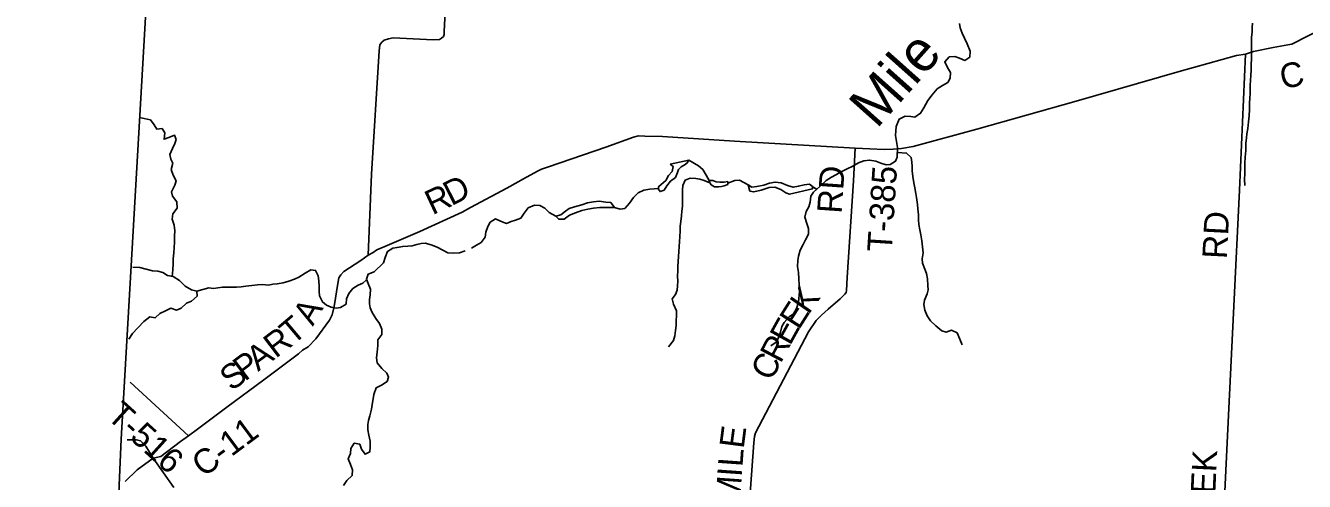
# Model space of a CAD drawing. Extents: x 1759416 to 2214760, y 252598 to 1116833.
# Drawn here: x 1928341 to 1943940, y 885193 to 890747 of the extents above; entities that cross this region are included whole.
import ezdxf

# ---------------------------------------------------------------- set-up
doc = ezdxf.new("R2010")
doc.units = 0
for name, color, linetype in [('GM_X_Adjacent_County', 7, 'Continuous'), ('GM_X_County', 7, 'Continuous'), ('GM_X_County_Road', 7, 'Continuous'), ('GM_X_County_Road_Text', 7, 'Continuous'), ('GM_X_Minor_Lake', 7, 'Continuous'), ('GM_X_Minor_River', 7, 'Continuous'), ('GM_X_Minor_River_Text', 7, 'Continuous'), ('GM_X_Township', 7, 'Continuous'), ('GM_X_Township_Road', 7, 'Continuous'), ('GM_X_Township_Road_Text', 7, 'Continuous')]:
    doc.layers.add(name, color=color, linetype=linetype)

msp = doc.modelspace()

# ---------------------------------------------------------------- linework, layer by layer
at = {"layer": 'GM_X_Adjacent_County'}
msp.add_lwpolyline([(1929994, 894165), (1929509, 885709), (1929483, 885147), (1929313, 880637), (1929312, 880613), (1928987, 876105), (1928954, 875572), (1928932, 875213), (1928849, 873883), (1928341, 865325)], dxfattribs=at)
at = {"layer": 'GM_X_County'}
msp.add_lwpolyline([(1928341, 865325), (1928849, 873883), (1928932, 875213), (1928954, 875572), (1928987, 876105), (1929312, 880613), (1929313, 880637), (1929483, 885147), (1929509, 885709), (1929994, 894165)], dxfattribs=at)
at = {"layer": 'GM_X_County_Road'}
for points in [[(1943220, 890401), (1943220, 890401), (1943318, 890430), (1943557, 890479), (1943736, 890512), (1943786, 890522), (1943987, 890621), (1944395, 890822)], [(1929555, 885194), (1929704, 885336), (1929899, 885475), (1929991, 885498), (1930230, 885678), (1930327, 885749), (1930438, 885830), (1930794, 886098), (1931246, 886433), (1931669, 886746), (1931717, 886793), (1931790, 886835), (1931880, 886932), (1932050, 887157), (1932081, 887223), (1932105, 887325), (1932148, 887605), (1932162, 887675), (1932185, 887709), (1932221, 887751), (1932432, 887885), (1932520, 887949), (1932579, 887984), (1932625, 888014), (1932725, 888057), (1933149, 888238), (1933665, 888474), (1933767, 888530), (1934213, 888768), (1934450, 888899), (1934595, 888979), (1934635, 888999), (1934718, 889028), (1935419, 889267), (1935756, 889386), (1935818, 889403), (1935896, 889401), (1936111, 889396), (1936988, 889341), (1938460, 889252), (1938638, 889245), (1938812, 889238), (1938925, 889243), (1939027, 889251), (1939169, 889272), (1939944, 889486), (1941157, 889825), (1942411, 890187), (1943112, 890383), (1943220, 890401)], [(1941368, 880620), (1941940, 881566), (1942051, 881746), (1942090, 881824), (1942112, 881902), (1942129, 882056), (1942148, 882437), (1942167, 882546), (1942181, 882630), (1942214, 882720), (1942261, 882832), (1942334, 882952), (1942494, 882949), (1942752, 882944), (1942810, 882939), (1942863, 882935), (1942887, 883358), (1942937, 884398), (1943014, 886001), (1943079, 887327), (1943149, 888741), (1943220, 890401)], [(1929581, 885699), (1929695, 885698), (1929744, 885687), (1929774, 885657), (1929808, 885621), (1929899, 885475)], [(1929899, 885475), (1930151, 885119)]]:
    msp.add_lwpolyline(points, dxfattribs=at)
at = {"layer": 'GM_X_Minor_Lake'}
for points in [[(1936203, 889059), (1936221, 889045), (1936239, 889031), (1936226, 888971), (1936182, 888920), (1936149, 888858), (1936095, 888811), (1936065, 888787), (1936059, 888757), (1936080, 888725), (1936130, 888741), (1936163, 888794), (1936209, 888852), (1936268, 888895), (1936294, 888956), (1936303, 888994), (1936339, 889026), (1936385, 889055), (1936411, 889073), (1936431, 889106)], [(1936431, 889106), (1936203, 889059)], [(1936908, 888848), (1936860, 888840), (1936810, 888839), (1936764, 888845), (1936724, 888858), (1936710, 888860), (1936684, 888858), (1936684, 888840), (1936704, 888808), (1936744, 888782), (1936791, 888783), (1936829, 888787), (1936861, 888796), (1936905, 888810)], [(1936905, 888810), (1936908, 888848)], [(1937174, 888729), (1937222, 888721), (1937312, 888740), (1937412, 888776), (1937482, 888780), (1937554, 888751), (1937613, 888708), (1937657, 888694), (1937939, 888757), (1937941, 888788), (1937904, 888815), (1937838, 888808), (1937768, 888792), (1937704, 888777), (1937634, 888798), (1937556, 888833), (1937483, 888841), (1937413, 888826), (1937347, 888803), (1937259, 888786), (1937199, 888779), (1937153, 888805)], [(1937153, 888805), (1937174, 888729)], [(1935526, 888532), (1935478, 888590), (1935418, 888595), (1935339, 888608), (1935269, 888599), (1935195, 888586), (1935125, 888564), (1935035, 888539), (1934973, 888520), (1934928, 888487), (1934870, 888442), (1934810, 888426)], [(1934810, 888426), (1934845, 888388), (1934909, 888387), (1934974, 888438), (1935050, 888467), (1935124, 888493), (1935198, 888510), (1935268, 888521), (1935346, 888530), (1935422, 888529), (1935464, 888531), (1935526, 888532)]]:
    msp.add_lwpolyline(points, dxfattribs=at)
at = {"layer": 'GM_X_Minor_River'}
for points in [[(1939733, 890771), (1939739, 890721), (1939766, 890653), (1939793, 890595), (1939827, 890525), (1939862, 890435), (1939859, 890363), (1939797, 890322), (1939731, 890352), (1939675, 890369), (1939607, 890366), (1939553, 890304), (1939588, 890236), (1939624, 890174), (1939617, 890106), (1939590, 890055), (1939526, 890019), (1939460, 889976), (1939401, 889905), (1939345, 889834), (1939296, 889747), (1939257, 889679), (1939187, 889632), (1939137, 889639), (1939069, 889644), (1938995, 889608), (1938960, 889517), (1938954, 889463), (1938951, 889410), (1938963, 889334), (1938976, 889260), (1938973, 889144), (1938952, 889094), (1938888, 889055), (1938838, 889050), (1938774, 889072), (1938713, 889095), (1938635, 889108), (1938565, 889099), (1938501, 889075), (1938425, 889032), (1938370, 889007), (1938296, 888968), (1938224, 888929), (1938172, 888900), (1938108, 888860), (1938033, 888789)], [(1943306, 890777), (1943304, 890724), (1943301, 890670), (1943294, 890602), (1943292, 890528), (1943294, 890409), (1943292, 890347), (1943291, 890269), (1943290, 890203), (1943286, 890145), (1943283, 890080), (1943279, 890022), (1943278, 889972), (1943276, 889920), (1943275, 889864), (1943269, 889801), (1943270, 889723), (1943265, 889647), (1943256, 889575), (1943248, 889494), (1943239, 889430), (1943232, 889378), (1943224, 889312), (1943223, 889227), (1943216, 889145), (1943211, 889071), (1943212, 888942), (1943207, 888876), (1943213, 888800)], [(1930129, 887691), (1930138, 887771), (1930141, 887847), (1930143, 887907), (1930150, 887979), (1930154, 888045), (1930157, 888109), (1930159, 888185), (1930160, 888245), (1930154, 888315), (1930131, 888390), (1930137, 888454), (1930192, 888522), (1930186, 888598), (1930135, 888670), (1930123, 888720), (1930160, 888802), (1930176, 888856), (1930143, 888924), (1930117, 888993), (1930136, 889071), (1930112, 889121), (1930099, 889177), (1930135, 889249), (1930162, 889309), (1930176, 889361), (1930159, 889411), (1930088, 889384), (1930030, 889362), (1930041, 889440), (1930007, 889494), (1929941, 889487), (1929911, 889537), (1929864, 889598), (1929748, 889624)], [(1938975, 889202), (1939087, 889193), (1939142, 889138), (1939152, 889084), (1939155, 889032), (1939155, 888976), (1939164, 888907), (1939177, 888833), (1939188, 888769), (1939198, 888703), (1939207, 888651), (1939220, 888567), (1939226, 888515), (1939231, 888441), (1939231, 888379), (1939236, 888325), (1939247, 888259), (1939259, 888199), (1939272, 888124), (1939281, 888052), (1939290, 887978), (1939278, 887904), (1939283, 887852), (1939310, 887778), (1939328, 887726), (1939343, 887662), (1939346, 887580), (1939350, 887528), (1939339, 887477), (1939305, 887403), (1939298, 887347), (1939309, 887278), (1939337, 887209), (1939378, 887151), (1939443, 887087), (1939515, 887026), (1939568, 887013), (1939636, 887035), (1939702, 887002), (1939737, 886926), (1939766, 886856)], [(1936431, 889106), (1936548, 889039), (1936600, 888995), (1936643, 888924), (1936684, 888851)], [(1936688, 888833), (1936617, 888859), (1936565, 888875), (1936515, 888884), (1936449, 888887), (1936385, 888864), (1936356, 888798), (1936352, 888748), (1936353, 888686), (1936355, 888615), (1936352, 888549), (1936347, 888487), (1936341, 888429), (1936334, 888362), (1936326, 888302), (1936325, 888248), (1936320, 888172), (1936318, 888118), (1936313, 888053), (1936309, 887995), (1936306, 887935), (1936301, 887873), (1936297, 887811), (1936296, 887758), (1936294, 887694), (1936295, 887634), (1936293, 887578), (1936288, 887522), (1936267, 887469), (1936229, 887417), (1936242, 887353), (1936280, 887273), (1936281, 887213), (1936278, 887150), (1936276, 887094), (1936269, 887034), (1936261, 886966), (1936244, 886909), (1936185, 886835)], [(1936906, 888828), (1936992, 888859), (1937050, 888864), (1937153, 888805)], [(1935526, 888532), (1935593, 888511), (1935649, 888519), (1935708, 888584), (1935758, 888653), (1935815, 888708), (1935883, 888741), (1935957, 888755), (1936060, 888762)], [(1938033, 888789), (1937952, 888719), (1937918, 888669), (1937913, 888595), (1937895, 888538), (1937862, 888484), (1937844, 888413), (1937869, 888337), (1937890, 888276), (1937892, 888205), (1937853, 888135), (1937824, 888080), (1937790, 888010), (1937769, 887939), (1937759, 887883), (1937758, 887813), (1937767, 887739), (1937772, 887660), (1937776, 887588), (1937779, 887506), (1937768, 887378), (1937743, 887301), (1937708, 887237), (1937656, 887198), (1937593, 887129), (1937567, 887079), (1937550, 887010), (1937532, 886960), (1937495, 886891), (1937433, 886846)], [(1937941, 888784), (1937992, 888754)], [(1933782, 888037), (1933840, 888070), (1933899, 888105), (1933947, 888169), (1933956, 888232), (1933978, 888298), (1934009, 888351), (1934071, 888393), (1934135, 888364), (1934208, 888337), (1934262, 888359), (1934318, 888378), (1934381, 888399), (1934423, 888462), (1934472, 888528), (1934550, 888559), (1934612, 888554), (1934675, 888523), (1934729, 888471), (1934810, 888426)], [(1933701, 888002), (1933635, 887978), (1933563, 887975), (1933493, 887977), (1933431, 888010), (1933363, 888048), (1933287, 888077), (1933216, 888095), (1933165, 888092), (1933113, 888078), (1933057, 888062), (1933003, 888059), (1932941, 888057), (1932873, 888044), (1932821, 888034), (1932755, 887996), (1932728, 887922), (1932708, 887857), (1932595, 887745), (1932520, 887720), (1932498, 887658), (1932520, 887603), (1932549, 887537), (1932544, 887467), (1932538, 887409), (1932536, 887359), (1932543, 887307), (1932569, 887251), (1932612, 887178), (1932658, 887116), (1932687, 887049), (1932687, 886985), (1932638, 886918), (1932638, 886851), (1932629, 886769), (1932621, 886697), (1932628, 886637), (1932686, 886571), (1932747, 886514), (1932767, 886464), (1932752, 886412), (1932684, 886366), (1932616, 886335), (1932587, 886251), (1932581, 886201), (1932568, 886129), (1932560, 886073), (1932539, 885993), (1932525, 885935), (1932516, 885885), (1932514, 885821), (1932527, 885755), (1932543, 885682), (1932546, 885614), (1932540, 885552), (1932482, 885524), (1932440, 885585), (1932417, 885647), (1932351, 885660), (1932308, 885596), (1932304, 885532), (1932277, 885470), (1932305, 885400), (1932330, 885333), (1932324, 885267), (1932259, 885206), (1932217, 885144)], [(1932501, 887649), (1932454, 887610), (1932397, 887584), (1932331, 887543), (1932285, 887483), (1932256, 887417), (1932252, 887353), (1932183, 887311), (1932133, 887306), (1932067, 887318), (1932013, 887339), (1931962, 887381), (1931928, 887455), (1931923, 887508), (1931921, 887570), (1931918, 887638), (1931910, 887698), (1931879, 887764), (1931821, 887771), (1931752, 887731), (1931674, 887680), (1931622, 887656), (1931553, 887632), (1931485, 887611), (1931409, 887599), (1931355, 887596), (1931305, 887586), (1931229, 887593), (1931171, 887587), (1931101, 887582), (1931029, 887574), (1930969, 887566), (1930913, 887561), (1930859, 887559), (1930801, 887560), (1930747, 887562), (1930687, 887552), (1930634, 887545), (1930575, 887551), (1930504, 887530), (1930430, 887510), (1930366, 887529), (1930287, 887571), (1930219, 887640), (1930141, 887689), (1930071, 887701), (1930016, 887738), (1929954, 887756), (1929888, 887760), (1929812, 887781), (1929733, 887798), (1929648, 887803)], [(1930430, 887510), (1930434, 887450), (1930365, 887388), (1930303, 887367), (1930237, 887305), (1930184, 887280), (1930112, 887306), (1930046, 887271), (1929978, 887239), (1929922, 887187), (1929856, 887198), (1929785, 887140), (1929711, 887065), (1929644, 886997), (1929599, 886928)]]:
    msp.add_lwpolyline(points, dxfattribs=at)
at = {"layer": 'GM_X_Township'}
msp.add_lwpolyline([(1956770, 893496), (1956600, 888493), (1956421, 883204), (1956242, 879261), (1950955, 879498), (1945394, 879799), (1941129, 880010), (1938954, 880144), (1938918, 880131), (1938742, 880137), (1937983, 880168), (1930902, 880556), (1929313, 880637), (1929483, 885147), (1929509, 885709), (1929994, 894165)], dxfattribs=at)
at = {"layer": 'GM_X_Township_Road'}
for points in [[(1933694, 896293), (1933714, 895816), (1933632, 894368), (1933567, 892964), (1933503, 891787), (1933448, 890674), (1933446, 890639), (1933438, 890616), (1933416, 890594), (1933388, 890578), (1933314, 890574), (1932826, 890599), (1932768, 890587), (1932716, 890569), (1932688, 890546), (1932663, 890514), (1932655, 890440), (1932562, 888938), (1932520, 887949)], [(1938460, 889252), (1938438, 888856), (1938361, 887679), (1938353, 887520), (1938349, 887496), (1938335, 887474), (1938278, 887419), (1938129, 887293), (1938050, 887218), (1937986, 887155), (1937891, 887017), (1937371, 886024), (1937245, 885784), (1937231, 885741), (1937222, 885665), (1937143, 884550), (1937106, 883741), (1937076, 883161)], [(1930327, 885749), (1929615, 886403)]]:
    msp.add_lwpolyline(points, dxfattribs=at)

# ---------------------------------------------------------------- texts
at = {"layer": 'GM_X_County_Road_Text'}
for s, rotation, p in [('C', 11.3375, (1943672, 889971)), ('R', 25.0848, (1933303, 888435)), ('D', 26.9886, (1933535, 888545)), ('RD', 87.0388, (1942993, 887899)), ('A', 60.0222, (1931845, 887077)), ('T', 40.1034, (1931600, 886846)), ('R', 37.2438, (1931391, 886686)), ('A', 36.7137, (1931177, 886527)), ('S', 36.7093, (1930853, 886285)), ('P', 36.7026, (1931015, 886406)), ('C-11', 36.7318, (1930512, 885235)), ('CREEK', 87.3698, (1942813, 884189))]:
    msp.add_text(s, height=300, rotation=rotation, dxfattribs=at).set_placement(p)
at = {"layer": 'GM_X_Minor_River_Text'}
msp.add_text('Mile', height=500.1, rotation=48.3343, dxfattribs=at).set_placement((1938721, 889480))
at = {"layer": 'GM_X_Township_Road_Text'}
for s, rotation, p in [('RD', 86.0551, (1938294, 888451)), ('T-385', 86.3536, (1938905, 887983)), ('K', 54.9934, (1937890, 887216)), ('E', 57.5485, (1937772, 887030)), ('E', 60.9004, (1937665, 886838)), ('R', 62.2253, (1937551, 886621)), ('C', 62.2427, (1937436, 886403)), ('T-516', 317.783, (1929319, 885972)), ('E', 82.7596, (1937100, 885585)), ('L', 85.9467, (1937085, 885365)), ('M', 86.0095, (1937054, 884918)), ('I', 86.0078, (1937076, 885243))]:
    msp.add_text(s, height=300, rotation=rotation, dxfattribs=at).set_placement(p)

doc.saveas('drawing.dxf')
